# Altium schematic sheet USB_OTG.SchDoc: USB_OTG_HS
size A4; DocumentNumber: MB1167; Revision: B.1; SheetNumber: 8; SheetTotal: 17; Project: STM327x6G-EVAL
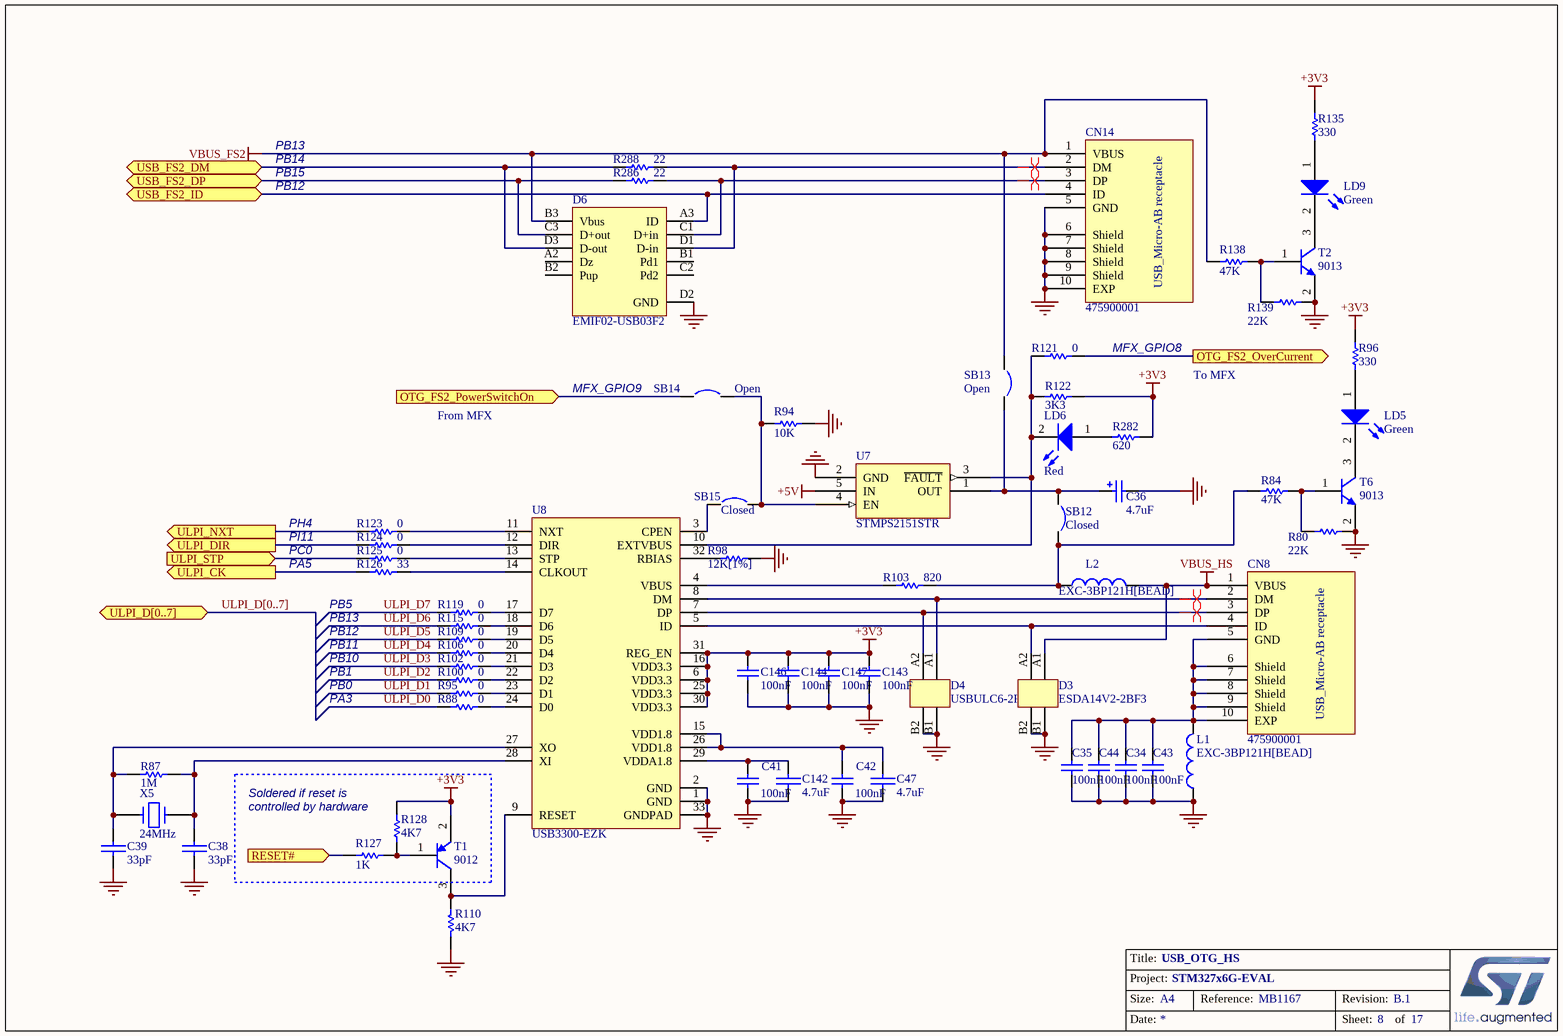
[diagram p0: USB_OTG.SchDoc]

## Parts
C34  100nF  [0603C]
C35  100nF  [0603C]
C36  4.7uF  [TAN-A]
C38  33pF  [0603C]
C39  33pF  [0603C]
C41  100nF  [0603C]
C42  100nF  [0603C]
C43  100nF  [0603C]
C44  100nF  [0603C]
C47  4.7uF  [TAN-A]
C142  4.7uF  [TAN-A]
C143  100nF  [0603C]
C144  100nF  [0603C]
C146  100nF  [0603C]
C147  100nF  [0603C]
CN8  475900001  [MOLEX_47590001]
CN14  475900001  [MOLEX_47590001]
D3  ESDA14V2-2BF3  [BGA4_0R4_0R8X0R8]
D4  USBULC6-2F3  [BGA4_0R4_1X1]
D6  EMIF02-USB03F2  [BGA11_0R5_1R57X2R07]
L1  EXC-3BP121H[BEAD]  [0603L]
L2  EXC-3BP121H[BEAD]  [0603L]
LD5  Green  [0603D]
LD6  Red  [0603D]
LD9  Green  [0603D]
R80  22K  [0603R]
R84  47K  [0603R]
R87  1M  [0603R]
R88  0  [0603R]
R94  10K  [0603R]
R95  0  [0603R]
R96  330  [0603R]
R98  12K[1%]  [0603R]
R100  0  [0603R]
R102  0  [0603R]
R103  820  [0603R]
R106  0  [0603R]
R109  0  [0603R]
R110  4K7  [0603R]
R115  0  [0603R]
R119  0  [0603R]
R121  0  [0603R]
R122  3K3  [0603R]
R123  0  [0603R]
R124  0  [0603R]
R125  0  [0603R]
R126  33  [0603R]
R127  1K  [0603R]
R128  4K7  [0603R]
R135  330  [0603R]
R138  47K  [0603R]
R139  22K  [0603R]
R282  620  [0603R]
R286  22  [0603R]
R288  22  [0603R]
SB12  Closed  [SB_0603]
SB13  Open  [SB_0603]
SB14  Open  [SB_0603]
SB15  Closed  [SB_0603]
T1  9012  [SOT-23]
T2  9013  [SOT-23]
T6  9013  [SOT-23]
U7  STMPS2151STR  [SOT23-5]
U8  USB3300-EZK  [QFN32_0R5_5X5]
X5  24MHz  [XTAL1]

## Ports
OTG_FS2_OverCurrent (out), OTG_FS2_PowerSwitchOn (in), RESET# (in), ULPI_CK (out), ULPI_D[0..7] (bidir), ULPI_DIR (out), ULPI_NXT (out), ULPI_STP (in), USB_FS2_DM (bidir), USB_FS2_DP (bidir), USB_FS2_ID (bidir)

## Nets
+3V3: C143.1 C144.1 C146.1 C147.1 R96.2 R122.1 R128.1 R135.2 R282.2 T1.2(E) U8.6(VDD3.3) U8.16(VDD3.3) U8.25(VDD3.3) U8.30(VDD3.3) U8.31(REG_EN)
+5V: U7.5(IN)
GND: C34.2 C35.2 C36.2 C38.2 C39.2 C41.2 C42.2 C43.2 C44.2 C47.2 C142.2 C143.2 C144.2 C146.2 C147.2 CN14.5(GND) CN14.6(Shield) CN14.7(Shield) CN14.8(Shield) CN14.9(Shield) CN14.10(EXP) D3.B1 D3.B2 D4.B1 D4.B2 D6.D2(GND) L1.1 R80.1 R94.1 R98.1 R110.1 R139.1 T2.2(E) T6.2(E) U7.2(GND) U8.1(GND) U8.2(GND) U8.33(GNDPAD)
VBUS_FS2: CN14.1(VBUS) D6.B3(Vbus) R138.1 SB13.1
VBUS_HS: CN8.1(VBUS) D3.A1 L2.2
OTG_FS2_OverCurrent: R121.1 ; port OTG_FS2_OverCurrent
OTG_FS2_PowerSwitchOn: SB14.1 ; port OTG_FS2_PowerSwitchOn
RESET#: R127.2 ; port RESET#
ULPI_CK: R126.2 ; port ULPI_CK
ULPI_D0: R88.2
ULPI_D1: R95.2
ULPI_D2: R100.2
ULPI_D3: R102.2
ULPI_D4: R106.2
ULPI_D5: R109.2
ULPI_D6: R115.2
ULPI_D7: R119.2
ULPI_DIR: R124.2 ; port ULPI_DIR
ULPI_NXT: R123.2 ; port ULPI_NXT
ULPI_STP: R125.2 ; port ULPI_STP
USB_FS2_DM: D6.D3(D-out) R288.2 ; port USB_FS2_DM
USB_FS2_DP: D6.C3(D+out) R286.2 ; port USB_FS2_DP
USB_FS2_ID: CN14.4(ID) D6.A3(ID) ; port USB_FS2_ID
NetC34_1: C34.1 C35.1 C43.1 C44.1 CN8.5(GND) CN8.6(Shield) CN8.7(Shield) CN8.8(Shield) CN8.9(Shield) CN8.10(EXP) L1.2
NetC36_1: C36.1 SB12.1 SB13.2 U7.1(OUT)
NetC38_1: C38.1 R87.2 U8.28(XI) X5.1
NetC39_1: C39.1 R87.1 U8.27(XO) X5.2
NetC41_1: C41.1 C142.1 U8.29(VDDA1.8)
NetC42_1: C42.1 C47.1 U8.15(VDD1.8) U8.26(VDD1.8)
NetCN8_2: CN8.2(DM) D4.A1 U8.8(DM)
NetCN8_3: CN8.3(DP) D4.A2 U8.7(DP)
NetCN8_4: CN8.4(ID) D3.A2 U8.5(ID)
NetCN14_2: CN14.2(DM) D6.D1(D-in) R288.1
NetCN14_3: CN14.3(DP) D6.C1(D+in) R286.1
NetL2_1: L2.1 R84.2 R103.2 SB12.2
NetLD5_1: LD5.1(A) R96.1
NetLD5_2: LD5.2(K) T6.3(C)
NetLD6_1: LD6.1(A) R282.1
NetLD6_2: LD6.2(K) R121.2 R122.2 U7.3(~{FAULT}) U8.10(EXTVBUS)
NetLD9_1: LD9.1(A) R135.1
NetLD9_2: LD9.2(K) T2.3(C)
NetR80_2: R80.2 R84.1 T6.1(B)
NetR88_1: R88.1 U8.24(D0)
NetR94_2: R94.2 SB14.2 SB15.2 U7.4(EN)
NetR95_1: R95.1 U8.23(D1)
NetR98_2: R98.2 U8.32(RBIAS)
NetR100_1: R100.1 U8.22(D2)
NetR102_1: R102.1 U8.21(D3)
NetR103_1: R103.1 U8.4(VBUS)
NetR106_1: R106.1 U8.20(D4)
NetR109_1: R109.1 U8.19(D5)
NetR110_2: R110.2 T1.3(C) U8.9(RESET)
NetR115_1: R115.1 U8.18(D6)
NetR119_1: R119.1 U8.17(D7)
NetR123_1: R123.1 U8.11(NXT)
NetR124_1: R124.1 U8.12(DIR)
NetR125_1: R125.1 U8.13(STP)
NetR126_1: R126.1 U8.14(CLKOUT)
NetR127_1: R127.1 R128.2 T1.1(B)
NetR138_2: R138.2 R139.2 T2.1(B)
NetSB15_1: SB15.1 U8.3(CPEN)

Not connected (* = marked no-connect by the designer): D6 A2(Dz) B1(Pd1) B2(Pup) C2(Pd2)

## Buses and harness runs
bus ULPI_D[0..7] = port ULPI_D[0..7]

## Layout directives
differential pair: NetCN8_2, NetCN8_3, NetCN14_2, NetCN14_3

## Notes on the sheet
- PB13
- PB14
- PB15
- PB12
- MFX_GPIO8
- To MFX
- From MFX
- MFX_GPIO9
- PH4
- PI11
- PC0
- PA5
- PB11
- PB5
- PA3
- PB0
- PB1
- PB10
- (near R128) Soldered if reset is
- (near R128) controlled by hardware

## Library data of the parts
C34 C35 C41-C44 C143 C144 C146 C147 = Cap: Capacitor; Value: 10nF
C36 = Cap Pol1: Polarized Capacitor (Radial); Value: 47uF
C38 C39 C47 C142 = CAP: Capacitor
L1 L2 = Inductor: Value: 100uH
LD5 LD6 LD9 = LED2: Typical RED, GREEN, YELLOW, AMBER GaAs LED
R80 R84 R94 R96 R103 R122 R135 R138 R139 = res1: Resistor; Value: 1K
R87 R88 R95 R98 R100 R102 R106 R109 R110 R115 R119 R121 R123-R126 R128 R282 R286 R288 = Res1: Resistor; Value: 1K
R127 = Res1: Resistor
SB12 SB15 = Circuit Breaker_close: Circuit Breaker
SB13 SB14 = Circuit Breaker
T1 = PNP: PNP Bipolar Transistor
T2 T6 = NPN: NPN Bipolar Transistor; Code - JEDEC: TO-226-AA
U7 = STMPS2141STR
X5 = CRYSTAL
